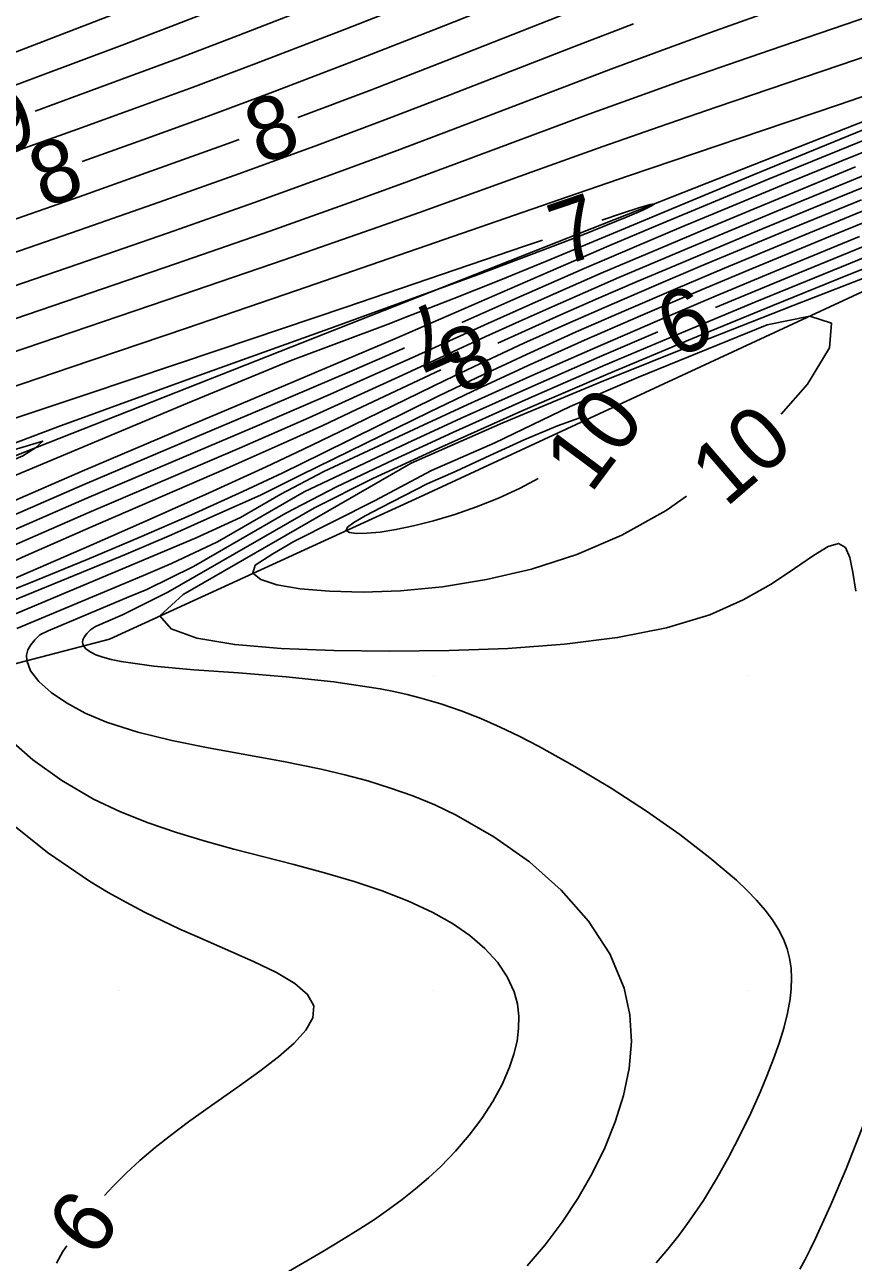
# Model space of a CAD drawing. Extents: x 2602990 to 2605851, y 618069 to 619180.
# Drawn here: x 2603216.97 to 2603243.37, y 618321.33 to 618360.74 of the extents above; entities that cross this region are included whole.
import ezdxf

# ---------------------------------------------------------------- set-up
doc = ezdxf.new("R2010")
doc.units = 0
for name, color, linetype in [('DTM Contours Major', 7, 'Continuous'), ('DTM Contours Major Text', 7, 'Continuous'), ('DTM Contours Minor', 7, 'Continuous'), ('DTM Contours Minor Text', 7, 'Continuous'), ('Exist DTM Drainline', 7, 'Continuous'), ('Exist DTM QL2 LIDAR Elevation Point', 7, 'Continuous'), ('Exist Roads EOP', 7, 'Continuous'), ('PH Exist DTM Breakline', 7, 'Continuous')]:
    doc.layers.add(name, color=color, linetype=linetype)

msp = doc.modelspace()

# ---------------------------------------------------------------- linework, layer by layer
at = {"layer": 'DTM Contours Major'}
for points in [[(2603232.042, 618350.596), (2603232.796, 618350.941), (2603234.02, 618351.488), (2603235.249, 618352.027), (2603236.484, 618352.559), (2603237.724, 618353.086), (2603240.316, 618354.172), (2603243.023, 618355.288), (2603245.739, 618356.391), (2603248.557, 618357.518), (2603251.681, 618358.75), (2603259.068, 618361.639), (2603269.134, 618365.569), (2603283.544, 618371.218), (2603285.941, 618372.151), (2603288.321, 618373.072), (2603290.658, 618373.969), (2603292.932, 618374.831), (2603294.547, 618375.436), (2603297.726, 618376.612), (2603305.437, 618379.437), (2603325.265, 618386.744)], [(2603275.946, 618376.566), (2603273.731, 618375.723), (2603271.513, 618374.867), (2603267.062, 618373.138), (2603264.824, 618372.273), (2603262.574, 618371.415), (2603260.163, 618370.511), (2603257.768, 618369.629), (2603255.419, 618368.776), (2603253.148, 618367.963), (2603250.987, 618367.198), (2603247.571, 618366.005), (2603244.375, 618364.896), (2603243.115, 618364.454), (2603241.834, 618363.997), (2603240.512, 618363.517), (2603239.134, 618363.003), (2603237.103, 618362.225), (2603234.953, 618361.384), (2603230.386, 618359.589), (2603228.019, 618358.671), (2603225.675, 618357.78)], [(2603223.799, 618357.088), (2603223.302, 618356.904), (2603220.989, 618356.071), (2603218.699, 618355.261), (2603212.091, 618352.955), (2603210.236, 618352.3), (2603208.425, 618351.656), (2603204.89, 618350.382), (2603200.146, 618348.649), (2603198.883, 618348.175), (2603197.592, 618347.672), (2603196.263, 618347.127), (2603194.885, 618346.526), (2603193.449, 618345.857), (2603191.596, 618344.727), (2603187.8, 618341.706)], [(2603215.017, 618342.933), (2603216.988, 618343.825), (2603219.076, 618344.739), (2603223.32, 618346.576), (2603225.335, 618347.468), (2603226.462, 618347.982), (2603227.541, 618348.484), (2603230.228, 618349.752)], [(2603234.811, 618348.274), (2603234.773, 618348.268), (2603233.944, 618347.968), (2603232.908, 618347.528), (2603231.789, 618347.022), (2603230.71, 618346.526), (2603229.796, 618346.117)], [(2603229.796, 618346.117), (2603228.322, 618345.37), (2603227.811, 618345.101), (2603227.453, 618344.893), (2603227.252, 618344.738), (2603227.211, 618344.63), (2603227.314, 618344.566), (2603227.539, 618344.537), (2603227.872, 618344.543), (2603228.296, 618344.585), (2603228.795, 618344.664), (2603229.354, 618344.779), (2603229.996, 618344.943), (2603230.672, 618345.147), (2603231.366, 618345.389), (2603232.064, 618345.668), (2603232.75, 618345.982), (2603233.331, 618346.287)]]:
    msp.add_lwpolyline(points, dxfattribs=at)
at = {"layer": 'DTM Contours Minor'}
for points in [[(2603230.899, 618351.261), (2603232.523, 618351.981), (2603234.797, 618352.972), (2603236.387, 618353.653), (2603237.889, 618354.288), (2603239.501, 618354.962), (2603241.21, 618355.669), (2603243.003, 618356.405), (2603244.868, 618357.163), (2603248.004, 618358.424), (2603250.561, 618359.439), (2603253.762, 618360.7), (2603260.83, 618363.464), (2603273.604, 618368.443), (2603287.265, 618373.796), (2603290.393, 618375.014), (2603293.467, 618376.203), (2603297.403, 618377.709), (2603300.32, 618378.809), (2603305.717, 618380.822), (2603313.054, 618383.538), (2603329.838, 618389.732)], [(2603238.982, 618351.734), (2603239.621, 618352.003), (2603241.64, 618352.839), (2603244.34, 618353.944), (2603247.34, 618355.154), (2603250.445, 618356.384), (2603260.34, 618360.258), (2603273.119, 618365.279), (2603276.379, 618366.555), (2603280.836, 618368.288), (2603283.497, 618369.311), (2603286.09, 618370.291), (2603287.416, 618370.786), (2603289.927, 618371.711), (2603292.552, 618372.665), (2603297.95, 618374.609), (2603303.224, 618376.505), (2603308.514, 618378.427), (2603321.931, 618383.339), (2603327.334, 618385.332)], [(2603278.586, 618381.696), (2603274.359, 618380.063), (2603271.308, 618378.867), (2603261.577, 618375.019), (2603258.513, 618373.816), (2603255.727, 618372.737), (2603254.294, 618372.191), (2603252.976, 618371.696), (2603250.634, 618370.833), (2603246.036, 618369.17), (2603244.593, 618368.636), (2603242.953, 618368.014), (2603242.033, 618367.658), (2603239.439, 618366.634), (2603229.996, 618362.845), (2603226.732, 618361.55), (2603223.628, 618360.343), (2603221.906, 618359.689), (2603220.263, 618359.076), (2603218.677, 618358.493), (2603217.297, 618357.991)], [(2603268.214, 618380.39), (2603266.551, 618379.727), (2603258.435, 618376.492), (2603254.775, 618375.038), (2603250.453, 618373.333), (2603246.232, 618371.683), (2603243.838, 618370.73), (2603240.938, 618369.559), (2603233.675, 618366.612), (2603229.728, 618365.015), (2603225.849, 618363.457), (2603222.246, 618362.028), (2603219.869, 618361.1), (2603215.419, 618359.389), (2603207.46, 618356.337), (2603204.769, 618355.31), (2603202.133, 618354.311), (2603197.891, 618352.72), (2603196.251, 618352.098), (2603194.676, 618351.476), (2603193.162, 618350.839), (2603191.704, 618350.169), (2603190.299, 618349.451), (2603188.941, 618348.673)], [(2603244.96, 618369.98), (2603242.977, 618369.207), (2603240.239, 618368.116), (2603229.892, 618363.942), (2603226.317, 618362.515), (2603222.972, 618361.202), (2603221.486, 618360.629), (2603220.072, 618360.092), (2603217.374, 618359.079), (2603212.308, 618357.187), (2603207.34, 618355.312), (2603198.436, 618351.931), (2603196.893, 618351.329), (2603195.399, 618350.719), (2603193.95, 618350.083), (2603192.538, 618349.405), (2603191.157, 618348.668), (2603189.587, 618347.726), (2603188.053, 618346.709)], [(2603243.647, 618365.864), (2603242.526, 618365.458), (2603241.349, 618365.024), (2603240.101, 618364.552), (2603237.863, 618363.685), (2603235.438, 618362.729), (2603230.246, 618360.669), (2603227.585, 618359.628), (2603224.952, 618358.621), (2603222.816, 618357.827), (2603220.731, 618357.071), (2603218.795, 618356.382)], [(2603230.119, 618361.756), (2603227.156, 618360.589), (2603224.282, 618359.482), (2603222.34, 618358.754), (2603220.469, 618358.068), (2603218.652, 618357.412), (2603213.34, 618355.522), (2603211.217, 618354.758), (2603209.086, 618353.981), (2603206.966, 618353.197), (2603204.876, 618352.41), (2603202.833, 618351.627), (2603200.858, 618350.853), (2603199.51, 618350.312), (2603198.194, 618349.762), (2603196.899, 618349.188), (2603195.616, 618348.573), (2603194.332, 618347.902), (2603193.039, 618347.159), (2603191.06, 618345.889), (2603189.056, 618344.485)], [(2603245.196, 618361.462), (2603241.459, 618360.187), (2603239.697, 618359.58), (2603237.983, 618358.982), (2603236.298, 618358.381), (2603234.943, 618357.886), (2603230.73, 618356.319), (2603229.209, 618355.758), (2603227.598, 618355.172), (2603224.778, 618354.17), (2603221.767, 618353.123), (2603218.668, 618352.06), (2603209.84, 618349.054)], [(2603240.403, 618361.053), (2603238.816, 618360.49), (2603237.226, 618359.913), (2603235.642, 618359.323), (2603230.635, 618357.416), (2603228.839, 618356.738), (2603226.957, 618356.041), (2603224.292, 618355.081), (2603221.516, 618354.104), (2603218.694, 618353.126), (2603210.612, 618350.359)], [(2603236.363, 618360.77), (2603234.482, 618360.044), (2603230.519, 618358.505), (2603228.44, 618357.708), (2603226.297, 618356.904), (2603223.795, 618355.991), (2603221.251, 618355.085), (2603218.699, 618354.192), (2603211.36, 618351.658), (2603209.621, 618351.052), (2603207.948, 618350.463), (2603206.326, 618349.886), (2603204.739, 618349.315), (2603203.171, 618348.744), (2603201.607, 618348.166), (2603200.495, 618347.751), (2603199.37, 618347.32), (2603198.225, 618346.864), (2603197.053, 618346.372), (2603195.847, 618345.834), (2603194.6, 618345.242), (2603192.83, 618344.221), (2603191.532, 618343.176)], [(2603245.13, 618360.195), (2603239.035, 618358.121), (2603237.182, 618357.485), (2603235.388, 618356.858), (2603233.136, 618356.054), (2603229.546, 618354.764), (2603228.217, 618354.293), (2603225.23, 618353.252), (2603221.975, 618352.135), (2603211.977, 618348.743)], [(2603214.784, 618348.597), (2603218.451, 618349.83), (2603222.122, 618351.074), (2603225.624, 618352.271), (2603229.785, 618353.708), (2603234.259, 618355.261), (2603236.211, 618355.927), (2603240.475, 618357.37), (2603242.896, 618358.193), (2603245.582, 618359.117)], [(2603245.089, 618357.969), (2603242.511, 618356.919), (2603240.211, 618355.971), (2603233.617, 618353.219), (2603232.087, 618352.594), (2603230.638, 618352.017), (2603229.108, 618351.424), (2603228.546, 618351.209), (2603225.422, 618350.04), (2603222.158, 618348.686), (2603206.058, 618341.943), (2603205.54, 618341.586), (2603205.039, 618341.391), (2603204.825, 618341.228), (2603204.716, 618340.856), (2603204.437, 618340.412), (2603204.204, 618339.899), (2603203.97, 618339.372), (2603203.688, 618338.883), (2603203.313, 618338.485), (2603202.797, 618338.233)], [(2603215.492, 618345.091), (2603218.797, 618346.519), (2603222.126, 618347.932), (2603225.278, 618349.262), (2603228.756, 618350.741), (2603233.645, 618352.864), (2603235.584, 618353.694), (2603237.146, 618354.354), (2603238.85, 618355.068), (2603240.685, 618355.829), (2603242.64, 618356.632), (2603244.704, 618357.472)], [(2603216.266, 618344.5), (2603218.95, 618345.663), (2603224.302, 618347.939), (2603226.711, 618348.976), (2603227.66, 618349.394), (2603229.395, 618350.172), (2603231.722, 618351.229), (2603233.53, 618352.035), (2603235.339, 618352.823), (2603237.225, 618353.628), (2603238.682, 618354.242), (2603240.21, 618354.88), (2603241.8, 618355.537), (2603243.44, 618356.209)], [(2603216.629, 618344.168), (2603219.011, 618345.204), (2603223.807, 618347.258), (2603226.023, 618348.225), (2603227.07, 618348.694), (2603229.004, 618349.58), (2603231.661, 618350.809), (2603232.72, 618351.289), (2603233.776, 618351.76), (2603234.835, 618352.224), (2603235.902, 618352.686), (2603238.088, 618353.616), (2603240.938, 618354.805), (2603243.907, 618356.024)], [(2603215.455, 618342.593), (2603219.081, 618344.17), (2603220.966, 618344.995), (2603222.84, 618345.829), (2603224.657, 618346.662), (2603225.855, 618347.227), (2603227.016, 618347.787), (2603230.375, 618349.422), (2603231.488, 618349.952), (2603232.875, 618350.595), (2603234.276, 618351.225), (2603235.682, 618351.842), (2603237.087, 618352.446), (2603238.484, 618353.036), (2603241.137, 618354.141), (2603243.629, 618355.163)], [(2603216.121, 618342.214), (2603218.781, 618343.297), (2603220.197, 618343.883), (2603221.641, 618344.498), (2603223.092, 618345.141), (2603224.478, 618345.761), (2603225.781, 618346.409), (2603229.85, 618348.402), (2603231.248, 618349.071), (2603233.011, 618349.889), (2603234.8, 618350.691), (2603236.587, 618351.471), (2603238.347, 618352.222), (2603240.054, 618352.938), (2603242.766, 618354.058), (2603245.778, 618355.282)], [(2603235.361, 618354.521), (2603235.978, 618354.727), (2603236.532, 618354.905), (2603236.892, 618355.011), (2603237.039, 618355.038), (2603236.959, 618354.978), (2603236.66, 618354.836), (2603236.162, 618354.622), (2603235.484, 618354.344), (2603234.645, 618354.011), (2603233.11, 618353.42), (2603231.364, 618352.767), (2603230.224, 618352.349), (2603226.539, 618351.018), (2603222.364, 618349.516), (2603218.018, 618347.932), (2603213.823, 618346.354)], [(2603215.754, 618342.418), (2603217.324, 618343.042), (2603218.954, 618343.706), (2603220.615, 618344.405), (2603222.279, 618345.129), (2603223.917, 618345.872), (2603225.192, 618346.474), (2603226.441, 618347.081), (2603230.138, 618348.906), (2603231.386, 618349.507), (2603232.953, 618350.238), (2603234.541, 618350.955), (2603236.132, 618351.654), (2603237.712, 618352.332), (2603239.264, 618352.986), (2603241.955, 618354.103), (2603244.225, 618355.031)], [(2603215.725, 618341.587), (2603222.429, 618344.395), (2603223.847, 618345.047), (2603225.13, 618345.786), (2603226.494, 618346.509), (2603229.524, 618347.923), (2603231.088, 618348.646), (2603233.066, 618349.538), (2603235.069, 618350.42), (2603237.059, 618351.278), (2603239.002, 618352.102), (2603240.86, 618352.88), (2603243.57, 618353.999)], [(2603232.979, 618321.218), (2603233.55, 618321.888), (2603234.09, 618322.604), (2603234.59, 618323.36), (2603235.045, 618324.152), (2603235.448, 618324.972), (2603235.785, 618325.8), (2603236.049, 618326.645), (2603236.226, 618327.499), (2603236.299, 618328.357), (2603236.253, 618329.212), (2603236.073, 618330.058), (2603235.615, 618331.148), (2603234.933, 618332.194), (2603234.065, 618333.177), (2603233.048, 618334.078), (2603231.919, 618334.881), (2603230.715, 618335.567), (2603230.03, 618335.892), (2603229.332, 618336.179), (2603228.623, 618336.432), (2603227.901, 618336.656), (2603227.166, 618336.855), (2603226.417, 618337.032), (2603225.215, 618337.277), (2603222.809, 618337.715), (2603221.656, 618337.946), (2603220.569, 618338.213), (2603219.574, 618338.533), (2603218.898, 618338.821), (2603218.303, 618339.14), (2603217.805, 618339.477), (2603217.417, 618339.823), (2603217.155, 618340.164), (2603217.031, 618340.489), (2603217.028, 618340.663), (2603217.071, 618340.83), (2603217.159, 618340.992), (2603217.287, 618341.15), (2603217.454, 618341.306), (2603217.712, 618341.44), (2603220.283, 618342.517), (2603220.859, 618342.755), (2603222.348, 618343.49), (2603225.291, 618345.181), (2603226.901, 618346.022), (2603228.714, 618346.881), (2603230.606, 618347.757), (2603233.022, 618348.839), (2603235.472, 618349.905), (2603237.896, 618350.933), (2603240.231, 618351.905), (2603242.416, 618352.8), (2603245.76, 618354.151)], [(2603237.084, 618321.313), (2603237.457, 618321.742), (2603237.808, 618322.183), (2603238.142, 618322.634), (2603238.593, 618323.302), (2603239.013, 618323.988), (2603239.404, 618324.685), (2603239.766, 618325.386), (2603240.101, 618326.082), (2603240.408, 618326.768), (2603240.629, 618327.292), (2603240.831, 618327.805), (2603241.009, 618328.304), (2603241.158, 618328.789), (2603241.276, 618329.26), (2603241.357, 618329.715), (2603241.393, 618330.05), (2603241.403, 618330.377), (2603241.385, 618330.697), (2603241.337, 618331.009), (2603241.258, 618331.316), (2603241.144, 618331.618), (2603240.987, 618331.929), (2603240.791, 618332.238), (2603240.558, 618332.546), (2603240.288, 618332.858), (2603239.983, 618333.173), (2603239.643, 618333.495), (2603238.803, 618334.214), (2603237.839, 618334.955), (2603236.78, 618335.699), (2603235.656, 618336.427), (2603234.498, 618337.122), (2603233.336, 618337.765), (2603232.724, 618338.079), (2603232.113, 618338.373), (2603231.497, 618338.644), (2603230.871, 618338.891), (2603230.227, 618339.113), (2603229.561, 618339.309), (2603229.15, 618339.414), (2603228.727, 618339.509), (2603228.294, 618339.595), (2603226.821, 618339.819), (2603225.295, 618339.978), (2603223.783, 618340.097), (2603222.357, 618340.201), (2603221.086, 618340.313), (2603220.039, 618340.459), (2603219.727, 618340.525), (2603219.457, 618340.598), (2603219.23, 618340.679), (2603219.05, 618340.766), (2603218.918, 618340.86), (2603218.837, 618340.96), (2603218.815, 618341.02), (2603218.809, 618341.082), (2603218.82, 618341.147), (2603218.847, 618341.214), (2603218.889, 618341.284), (2603218.947, 618341.358), (2603219.06, 618341.474), (2603219.223, 618341.581), (2603220.082, 618341.943), (2603221.526, 618342.668), (2603226.204, 618345.359), (2603228.056, 618346.287), (2603230.158, 618347.258), (2603232.844, 618348.455), (2603235.563, 618349.626), (2603238.242, 618350.75), (2603240.807, 618351.803), (2603243.185, 618352.763), (2603246.816, 618354.207)], [(2603214.706, 618347.563), (2603218.927, 618348.968), (2603223.162, 618350.388), (2603227.167, 618351.738), (2603232.925, 618353.695), (2603233.467, 618353.879)], [(2603243.449, 618342.701), (2603243.354, 618343.3), (2603243.254, 618343.776), (2603243.116, 618344.096), (2603242.902, 618344.223), (2603242.566, 618344.128), (2603242.1, 618343.842), (2603241.499, 618343.423), (2603240.754, 618342.929), (2603239.857, 618342.42), (2603238.801, 618341.952), (2603237.418, 618341.531), (2603235.86, 618341.222), (2603234.163, 618341.009), (2603232.362, 618340.876), (2603230.493, 618340.808), (2603228.594, 618340.79), (2603226.821, 618340.809), (2603225.144, 618340.873), (2603223.659, 618341), (2603222.456, 618341.205), (2603221.629, 618341.503), (2603221.271, 618341.911), (2603222.013, 618342.6), (2603229.282, 618346.778), (2603232.203, 618348.066), (2603235.338, 618349.367), (2603238.456, 618350.621), (2603241.458, 618351.802), (2603244.245, 618352.882)], [(2603241.075, 618348.333), (2603241.912, 618349.295), (2603242.609, 618350.454), (2603242.677, 618351.233), (2603241.982, 618351.462), (2603240.621, 618351.186), (2603236.525, 618349.511), (2603234.35, 618348.586), (2603231.95, 618347.426), (2603229.933, 618346.543)], [(2603216.721, 618341.516), (2603220.755, 618343.204), (2603221.643, 618343.577), (2603223.106, 618344.273), (2603225.875, 618345.863), (2603229.153, 618347.409), (2603230.875, 618348.206), (2603233.065, 618349.192), (2603235.285, 618350.163), (2603237.14, 618350.957)], [(2603215.894, 618344.813), (2603218.887, 618346.107), (2603221.91, 618347.391), (2603224.799, 618348.611), (2603227.39, 618349.716), (2603229.007, 618350.421), (2603229.071, 618350.45)], [(2603217.314, 618347.268), (2603217.542, 618347.481), (2603216.076, 618347.04), (2603213.491, 618346.161), (2603210.362, 618345.054), (2603207.264, 618343.934), (2603204.772, 618343.012), (2603203.84, 618342.657), (2603203.202, 618342.401), (2603202.973, 618342.302), (2603202.691, 618342.167), (2603202.54, 618342.08), (2603202.487, 618342.042), (2603202.446, 618342.006), (2603202.414, 618341.973), (2603202.378, 618341.918), (2603202.356, 618341.865), (2603202.326, 618341.749), (2603202.303, 618341.683), (2603202.266, 618341.607), (2603202.206, 618341.516), (2603202.044, 618341.314), (2603202.027, 618341.294)], [(2603203.265, 618341.434), (2603204.428, 618341.883), (2603204.787, 618342.024), (2603206.199, 618342.602), (2603211.957, 618344.935), (2603214.889, 618346.143), (2603216.91, 618347.012), (2603217.314, 618347.268)], [(2603229.933, 618346.543), (2603228.117, 618345.581), (2603225.54, 618344.279), (2603224.869, 618343.893), (2603224.311, 618343.524), (2603224.241, 618343.27), (2603224.489, 618343.069), (2603225.004, 618342.901), (2603225.746, 618342.774), (2603226.677, 618342.696), (2603227.755, 618342.674), (2603228.943, 618342.717), (2603230.283, 618342.844), (2603231.68, 618343.068), (2603233.113, 618343.406), (2603234.559, 618343.874), (2603235.999, 618344.488), (2603237.411, 618345.265), (2603238.057, 618345.727)], [(2603225.24, 618320.961), (2603226.468, 618321.671), (2603227.066, 618322.029), (2603227.65, 618322.393), (2603228.111, 618322.696), (2603228.561, 618323.007), (2603228.999, 618323.33), (2603229.422, 618323.665), (2603229.831, 618324.014), (2603230.224, 618324.38), (2603230.696, 618324.867), (2603231.133, 618325.377), (2603231.531, 618325.906), (2603231.882, 618326.447), (2603232.18, 618326.994), (2603232.419, 618327.543), (2603232.557, 618327.957), (2603232.654, 618328.367), (2603232.706, 618328.772), (2603232.711, 618329.17), (2603232.665, 618329.559), (2603232.564, 618329.939), (2603232.344, 618330.423), (2603232.03, 618330.886), (2603231.629, 618331.324), (2603231.148, 618331.736), (2603230.594, 618332.119), (2603229.972, 618332.471), (2603229.198, 618332.83), (2603228.358, 618333.155), (2603227.462, 618333.452), (2603226.522, 618333.728), (2603225.547, 618333.993), (2603223.635, 618334.489), (2603222.717, 618334.739), (2603221.803, 618335.012), (2603220.901, 618335.32), (2603220.017, 618335.672), (2603219.16, 618336.08), (2603218.151, 618336.668), (2603217.231, 618337.325), (2603216.441, 618338.021)], [(2603219.507, 618323.453), (2603219.785, 618323.758), (2603220.195, 618324.169), (2603220.632, 618324.571), (2603221.129, 618324.99), (2603221.65, 618325.399), (2603222.188, 618325.799), (2603222.733, 618326.19), (2603223.816, 618326.952), (2603224.462, 618327.416), (2603225.05, 618327.867), (2603225.548, 618328.303), (2603225.923, 618328.722), (2603226.143, 618329.119), (2603226.175, 618329.493), (2603225.983, 618329.86), (2603225.578, 618330.21), (2603224.99, 618330.557), (2603224.252, 618330.912), (2603222.447, 618331.701), (2603221.908, 618331.942), (2603221.354, 618332.201), (2603220.787, 618332.48), (2603220.209, 618332.782), (2603219.623, 618333.11), (2603219.031, 618333.468), (2603217.691, 618334.384), (2603216.408, 618335.412)], [(2603241.669, 618321.107), (2603241.832, 618321.413), (2603241.997, 618321.739), (2603242.165, 618322.085), (2603242.645, 618323.133), (2603243.143, 618324.309), (2603243.643, 618325.584), (2603244.127, 618326.93), (2603244.579, 618328.318), (2603244.983, 618329.719), (2603245.286, 618330.946), (2603245.306, 618331.047)], [(2603217.975, 618321.306), (2603218.186, 618321.671), (2603218.304, 618321.858)]]:
    msp.add_lwpolyline(points, dxfattribs=at)
at = {"layer": 'Exist DTM Drainline'}
msp.add_lwpolyline([(2603204.098, 618342.063), (2603247.886, 618359.31), (2603300.002, 618379.256), (2603348.063, 618397.511), (2603388.725, 618412.554), (2603432.793, 618429.056), (2603474.09, 618444.074), (2603510.151, 618459.891), (2603545.952, 618474.924)], dxfattribs=at)
at = {"layer": 'Exist DTM QL2 LIDAR Elevation Point'}
for p, q in [((2603230, 618340), (2603230, 618340)), ((2603240, 618340), (2603240, 618340)), ((2603220, 618330), (2603220, 618330)), ((2603230, 618330), (2603230, 618330)), ((2603240, 618330), (2603240, 618330))]:
    msp.add_line(p, q, dxfattribs=at)
at = {"layer": 'Exist Roads EOP'}
msp.add_spline([(2604034.633, 618668.486), (2603984.89, 618650.123), (2603936.767, 618631.654), (2603888.195, 618613.335), (2603837.766, 618594.258), (2603782.918, 618573.705), (2603731.939, 618554.39), (2603671.126, 618532.171), (2603621.822, 618514.106), (2603561.545, 618491.877), (2603506.421, 618471.293), (2603452.163, 618451.33), (2603398.364, 618431.316), (2603341.431, 618410.355), (2603281.65, 618388.199), (2603223.033, 618366.475), (2603185.717, 618352.612)], degree=3, dxfattribs=at)
at = {"layer": 'PH Exist DTM Breakline'}
msp.add_lwpolyline([(2603546.278, 618467.89), (2603526.855, 618460.306), (2603507.213, 618451.651), (2603485.725, 618442.619), (2603466.383, 618433.876), (2603454.696, 618429.386), (2603442.234, 618424.385), (2603428.822, 618418.102), (2603416.965, 618413.956), (2603393.207, 618405.535), (2603378.639, 618399.772), (2603357.505, 618392.883), (2603332.502, 618384.211), (2603305.954, 618375.46), (2603282.242, 618367.811), (2603247.909, 618354.209), (2603229.683, 618345.761), (2603219.668, 618341.177), (2603212.41, 618339.282), (2603206.143, 618338.068)], dxfattribs=at)

# ---------------------------------------------------------------- texts
at = {"layer": 'DTM Contours Major Text'}
for s, rotation, p in [('8', 20.2721, (2603224.47, 618356.269)), ('8', 204.9489, (2603231.304, 618351.359)), ('10', 53.3119, (2603235.004, 618345.775))]:
    msp.add_text(s, height=2, rotation=rotation, dxfattribs=at).set_placement(p)
at = {"layer": 'DTM Contours Minor Text'}
for s, rotation, p in [('9', 19.9841, (2603216.085, 618356.486)), ('8', 19.3423, (2603217.566, 618354.891)), ('7', 18.7401, (2603234.116, 618353.043)), ('9', 202.8718, (2603238.274, 618352.522)), ('7', 203.923, (2603230.177, 618352.034)), ('10', 40.8077, (2603239.309, 618345.34)), ('9', 232.9681, (2603218.468, 618323.804))]:
    msp.add_text(s, height=2, rotation=rotation, dxfattribs=at).set_placement(p)

doc.saveas('drawing.dxf')
